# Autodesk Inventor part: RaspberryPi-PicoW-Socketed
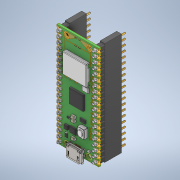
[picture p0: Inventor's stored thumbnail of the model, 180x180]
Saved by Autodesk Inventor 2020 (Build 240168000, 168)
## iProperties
Created: 2023-08
Part Number: RaspberryPi-PicoW-Socketed
Material: Générique
Document SubType Name: Modeling
Designer: bruno
Density: 1 g/cm^3
Appearance: Par défaut
Title: RaspberryPi-PicoW-Socketed
Revision Number: AFirst version
Sending System: Rhino 7.33
Preprocessor: ST-DEVELOPER v16.5
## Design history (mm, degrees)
fillet "brep_1"
fillet "brep_2"
fillet "brep_3"
fillet "brep_4"
fillet "brep_5"
fillet "brep_6"
fillet "brep_7"
fillet "brep_8"
fillet "brep_9"
fillet "brep_10"
fillet "brep_11"
fillet "brep_12"
fillet "brep_13"
fillet "brep_14"
fillet "brep_15"
fillet "brep_16"
fillet "brep_17"
fillet "brep_18"
fillet "brep_19"
fillet "brep_20"
fillet "brep_21"
fillet "brep_22"
fillet "brep_23"
fillet "brep_24"
fillet "brep_25"
fillet "brep_26"
fillet "brep_27"
fillet "brep_28"
fillet "LPattern6[1]"
fillet "LPattern5[2]"
fillet "Chamfer6"
fillet "LPattern5[1]"
fillet "Fillet6"
fillet "LPattern6[2]"
fillet "Fillet2"
fillet "brep_36"
fillet "brep_37"
fillet "brep_38"
fillet "brep_39"
fillet "brep_40"
fillet "brep_41"
fillet "brep_42"
fillet "brep_43"
fillet "brep_44"
fillet "brep_45"
fillet "brep_46"
fillet "brep_47"
fillet "brep_48"
fillet "brep_49"
fillet "brep_50"
fillet "brep_51"
fillet "brep_52"
fillet "brep_53"
fillet "brep_54"
fillet "brep_55"
fillet "brep_56"
fillet "brep_57"
fillet "brep_58"
fillet "brep_59"
fillet "brep_60"
fillet "brep_61"
fillet "brep_62"
fillet "brep_63"
fillet "brep_64"
fillet "brep_65"
fillet "brep_66"
fillet "brep_67"
fillet "brep_68"
fillet "brep_69"
fillet "brep_70"
fillet "brep_71"
fillet "brep_72"
fillet "brep_73"
fillet "brep_74"
fillet "brep_75"
fillet "brep_76"
fillet "brep_77"
fillet "brep_78"
fillet "brep_79"
node "Solide1"
node "Solide2"
node "Solide3"
node "Solide4"
node "Solide5"
node "Solide6"
node "Solide7"
node "Solide8"
node "Solide9"
node "Solide10"
node "Solide11"
node "Solide12"
node "Solide13"
node "Solide14"
node "Solide15"
node "Solide16"
node "Solide17"
node "Solide18"
node "Solide19"
node "Solide20"
node "Solide21"
node "Solide22"
node "Solide23"
node "Solide24"
node "Solide25"
node "Solide26"
node "Solide27"
node "Solide28"
node "Solide29"
node "Solide30"
node "Solide31"
node "Solide32"
node "Solide33"
node "Solide34"
node "Solide35"
node "Solide36"
node "Solide37"
node "Solide38"
node "Solide39"
node "Solide40"
node "Solide41"
node "Solide42"
node "Solide43"
node "Solide44"
node "Solide45"
node "Solide46"
node "Solide47"
node "Solide48"
node "Solide49"
node "Solide50"
node "Solide51"
node "Solide52"
node "Solide53"
node "Solide54"
node "Solide55"
node "Solide56"
node "Solide57"
node "Solide58"
node "Solide59"
node "Solide60"
node "Solide61"
node "Solide62"
node "Solide63"
node "Solide64"
node "Solide65"
node "Solide66"
node "Solide67"
node "Solide68"
node "Solide69"
node "Solide70"
node "Solide71"
node "Solide72"
node "Solide73"
node "Solide74"
node "Solide75"
node "Solide76"
node "Solide77"
node "Solide78"
node "Solide79"
